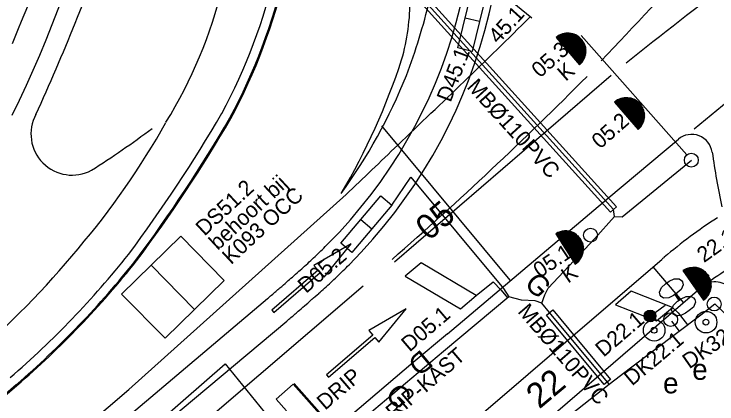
# Model space of a CAD drawing. Extents: x 81617 to 82144, y 454649 to 455150.
# Drawn here: x 81836.93 to 81870.9, y 454846.75 to 454865.61 of the extents above; entities that cross this region are included whole.
import ezdxf

# ---------------------------------------------------------------- set-up
doc = ezdxf.new("R2010")
doc.units = 0
for name, color, linetype in [('B-WE-OG-TOPOGRAFIE-G', 7, 'Continuous'), ('B-WE-VW-MARKERING-G', 7, 'Continuous'), ('N-OI-KL-VRI_KABEL_DETECTIE-G', 7, 'Continuous'), ('N-OI-KL-VRI_KABELGEUL-G', 7, 'Continuous'), ('N-OI-KL-VRI_LUS_DETECTIE-G', 7, 'Continuous'), ('N-OI-KL-VRI_LUS_DETECTIE-T18', 7, 'Continuous'), ('N-OI-KL-VRI_LUS_DETECTIE_SELECTIEF-G', 7, 'Continuous'), ('N-OI-KL-VRI_LUS_DETECTIE_SELECTIEF-T18', 7, 'Continuous'), ('N-OI-KL-VRI_MANTELBUIS-G', 7, 'Continuous'), ('N-OI-KL-VRI_MANTELBUIS-T18', 7, 'Continuous'), ('N-WE-VW-VRI_ARMATUUR-S', 7, 'Continuous'), ('N-WE-VW-VRI_ARMATUUR-T18', 7, 'Continuous'), ('N-WE-VW-VRI_KAST-T25', 7, 'Continuous'), ('N-WE-VW-VRI_LIGGER-G', 7, 'Continuous'), ('N-WE-VW-VRI_MAST-S', 7, 'Continuous'), ('N-WE-VW-VRI_RICHTINGNUMMER-T25', 7, 'Continuous')]:
    doc.layers.add(name, color=color, linetype=linetype)

msp = doc.modelspace()

# ---------------------------------------------------------------- linework, layer by layer
at = {"layer": 'B-WE-OG-TOPOGRAFIE-G'}
for p, q in [((81865.678, 454856.743), (81869.042, 454859.555)), ((81857.883, 454850.147), (81865.678, 454856.743)), ((81841.457, 454845.317), (81849.178, 454851.845)), ((81842.185, 454844.105), (81850.112, 454850.755)), ((81805.998, 454821.061), (81837.039, 454847.68))]:
    msp.add_line(p, q, dxfattribs=at)
for points in [[(81844.903, 454886.604), (81839.743, 454871.882), (81839.482, 454871.138), (81839.219, 454870.396), (81838.954, 454869.656), (81838.687, 454868.917), (81838.416, 454868.18), (81838.141, 454867.445), (81837.861, 454866.713), (81837.575, 454865.984), (81837.282, 454865.256), (81837.135, 454864.898), (81836.833, 454864.175)], [(81846.257, 454886.129), (81841.097, 454871.407), (81840.835, 454870.661), (81840.571, 454869.915), (81840.304, 454869.17), (81840.035, 454868.425), (81839.761, 454867.681), (81839.483, 454866.937), (81839.199, 454866.195), (81838.909, 454865.455), (81838.612, 454864.716), (81838.461, 454864.348), (81838.153, 454863.613), (81837.836, 454862.881), (81837.509, 454862.152), (81837.173, 454861.427), (81836.825, 454860.707)], [(81800.623, 454800), (81801.004, 454800.325), (81803.562, 454802.106), (81806.327, 454803.545), (81807.843, 454804.154), (81811.662, 454806.006), (81813.175, 454806.868), (81815.707, 454808.644), (81816.429, 454809.247), (81868.254, 454853.758)], [(81870.182, 454852.409), (81817.99, 454807.424), (81817.086, 454806.655), (81814.618, 454804.918), (81812.282, 454803.586), (81808.553, 454801.84), (81808.014, 454801.627)], [(81857.884, 454850.147), (81856.226, 454848.756), (81836.105, 454831.612)]]:
    msp.add_lwpolyline(points, dxfattribs=at)
for centre, radius, start, end in [((81834.856, 454871.629), 25.75, 315.1816, 14.1581), ((81834.856, 454871.629), 24.315, 315.1816, 14.1581), ((81744.949, 454903.377), 102.333, 335.38677, 340.77263), ((81821.582, 454874.325), 28.769, 331.9437, 346.7819), ((81821.582, 454874.325), 29.219, 331.9437, 346.7819), ((81824.821, 454872.343), 22.839, 328.39, 346.2989), ((81783.595, 454897.814), 73.395, 323.31793, 329.72379), ((81839.74, 454859.812), 1.994, 151.7295, 298.0081), ((81783.595, 454897.814), 73.845, 323.31793, 329.72379), ((81811.007, 454878.951), 38.102, 319.6035, 330.8163), ((81814.671, 454898.789), 48.33, 302.5532, 306.7699), ((81869.683, 454858.788), 1, 8.1206, 129.8961), ((81909.402, 454864.455), 39.12, 188.1206, 192.063), ((81883.766, 454835.824), 23.708, 122.7903, 130.5415), ((81834.293, 454872.188), 25.109, 314.3259, 315.1816), ((81807.049, 454881.413), 42.717, 310.5127, 320.5293), ((81831.414, 454875.136), 29.23, 313.5314, 314.3259), ((81807.67, 454881.636), 44.445, 310.8557, 321.5233), ((81807.67, 454881.636), 44.895, 310.8557, 321.5233), ((81825.018, 454881.985), 38.601, 312.248, 312.8592), ((81829.656, 454876.987), 31.783, 312.8592, 313.5314), ((81883.838, 454834.715), 24.607, 128.9896, 129.2958), ((81822.016, 454885.29), 43.065, 311.7591, 312.248), ((81834.293, 454872.188), 26.544, 314.3259, 315.1816), ((81813.097, 454895.28), 56.458, 311.3313, 311.7591), ((81831.414, 454875.136), 30.665, 313.5314, 314.3259), ((81878.198, 454841.916), 13.204, 120.9031, 127.375), ((81782.192, 454930.722), 103.482, 310.78124, 311.0257), ((81806.807, 454902.432), 65.982, 311.0257, 311.33128), ((81825.018, 454881.985), 40.036, 312.248, 312.8592), ((81829.656, 454876.987), 33.218, 312.8592, 313.5314), ((81870.835, 454851.651), 1, 35.4028, 130.7582), ((81768.584, 454946.497), 124.315, 310.65901, 310.78124), ((81822.016, 454885.29), 44.5, 311.7591, 312.248), ((81524.251, 455230.972), 499.315, 310.5979, 310.65901), ((81813.097, 454895.28), 57.893, 311.33128, 311.75909), ((81806.807, 454902.432), 67.417, 311.0257, 311.33128), ((81768.584, 454946.497), 125.75, 310.65901, 310.78124), ((81782.192, 454930.722), 104.917, 310.78124, 311.0257), ((81524.251, 455230.972), 500.75, 310.5979, 310.65901)]:
    msp.add_arc(centre, radius, start, end, dxfattribs=at)
at = {"layer": 'B-WE-VW-MARKERING-G'}
for p, q in [((81869.8, 454860.056), (81874.825, 454864.194)), ((81855.317, 454853.619), (81865.787, 454862.653)), ((81854.691, 454860.197), (81860.888, 454852.73)), ((81867.811, 454853.377), (81869.284, 454851.635)), ((81846.116, 454845.885), (81853.81, 454852.455)), ((81799.634, 454815.526), (81837.071, 454847.642))]:
    msp.add_line(p, q, dxfattribs=at)
msp.add_lwpolyline([(81801.861, 454812.865), (81812.709, 454822.091), (81823.285, 454831.011), (81833.469, 454839.753), (81842.474, 454847.451), (81852.979, 454856.88)], dxfattribs=at)
for points in [[(81853.227, 454854.493), (81851.427, 454853.442), (81851.623, 454853.214), (81849.385, 454851.292), (81849.482, 454851.178), (81851.721, 454853.1), (81851.916, 454852.873)], [(81855.876, 454851.355), (81854.076, 454850.304), (81854.272, 454850.077), (81852.034, 454848.155), (81852.131, 454848.041), (81854.37, 454849.963), (81854.565, 454849.735)]]:
    msp.add_lwpolyline(points, close=True, dxfattribs=at)
for centre, radius, start, end in [((81999.362, 454697.85), 212.13, 125.19968, 128.77534), ((81664.878, 455054.559), 277.009, 316.35043, 317.79319), ((81821.582, 454874.325), 29.269, 331.9437, 346.7819), ((81845.809, 454866.259), 10.261, 343.8323, 0.6213), ((81823.555, 454874.579), 34.479, 339.7444, 346.0669), ((81512.43, 455220.159), 497.913, 313.54801, 314.57127), ((81824.431, 454873.61), 32.859, 329.5018, 341.9003), ((81830.91, 454872.739), 26.954, 324.0988, 338), ((81737.068, 454988.961), 179.553, 311.14097, 315.26873), ((81783.595, 454897.814), 73.895, 323.31793, 329.72379), ((81783.595, 454897.814), 73.895, 323.31793, 329.72379), ((81697.039, 455021.878), 227.028, 313.38316, 314.25554), ((81807.67, 454881.636), 44.945, 310.8557, 321.5233)]:
    msp.add_arc(centre, radius, start, end, dxfattribs=at)
at = {"layer": 'N-OI-KL-VRI_KABEL_DETECTIE-G'}
msp.add_line((81868.754, 454851.421), (81869.03, 454851.16), dxfattribs=at)
for points in [[(81855.198, 454856.363), (81856.111, 454857.715), (81856.111, 454857.715), (81860.586, 454852.335)], [(81859.274, 454851.998), (81860.089, 454852.659), (81860.471, 454852.247)], [(81841.927, 454844.135), (81847.132, 454848.689), (81850.902, 454844.037)]]:
    msp.add_lwpolyline(points, dxfattribs=at)
at = {"layer": 'N-OI-KL-VRI_KABELGEUL-G'}
msp.add_line((81869.03, 454851.16), (81869.475, 454850.571), dxfattribs=at)
for points in [[(81862.44, 454851.616), (81862.582, 454852.027), (81862.754, 454852.346), (81865.008, 454854.754), (81865.955, 454855.815), (81865.903, 454856.153), (81846.599, 454877.513), (81846.252, 454877.634), (81845.96, 454877.281), (81846.114, 454876.473)], [(81870.802, 454851.587), (81872.685, 454849.803), (81872.834, 454849.851), (81878.298, 454853.089), (81882.037, 454855.056), (81886.495, 454859.072)], [(81865.955, 454855.815), (81866.324, 454855.794), (81869.674, 454858.544)], [(81860.586, 454852.335), (81860.85, 454851.931)], [(81860.471, 454852.247), (81860.783, 454851.875)], [(81865.692, 454847.708), (81862.812, 454851.166), (81862.44, 454851.616), (81862.125, 454851.74), (81861.458, 454851.771), (81860.85, 454851.931), (81857.688, 454849.285), (81854.312, 454846.452), (81850.918, 454843.526), (81850.644, 454843.845)], [(81870.121, 454851.062), (81870.802, 454851.587)], [(81831.652, 454818.786), (81838.237, 454824.448), (81844.551, 454829.887), (81846.588, 454831.607), (81850.757, 454835.251), (81862.252, 454844.975), (81865.692, 454847.708), (81866.725, 454848.497), (81870.121, 454851.062)], [(81868.713, 454850.754), (81869.077, 454850.271)]]:
    msp.add_lwpolyline(points, dxfattribs=at)
at = {"layer": 'N-OI-KL-VRI_LUS_DETECTIE-G'}
for p, q in [((81858.741, 454865.428), (81859.421, 454865.262)), ((81853.691, 454855.675), (81854.225, 454855.221)), ((81856.602, 454853.572), (81855.839, 454852.924)), ((81859.274, 454851.998), (81856.602, 454853.572)), ((81855.839, 454852.924), (81858.509, 454851.351)), ((81858.509, 454851.351), (81859.274, 454851.998)), ((81866.765, 454852.196), (81866.003, 454851.547)), ((81868.754, 454851.421), (81866.765, 454852.196)), ((81866.003, 454851.547), (81867.989, 454850.774)), ((81867.989, 454850.774), (81868.754, 454851.421))]:
    msp.add_line(p, q, dxfattribs=at)
for points in [[(81859.066, 454863.805), (81858.387, 454863.97), (81859.095, 454866.885), (81859.776, 454866.72)], [(81853.252, 454854.079), (81852.719, 454854.533), (81854.664, 454856.817), (81855.198, 454856.363)]]:
    msp.add_lwpolyline(points, close=True, dxfattribs=at)
at = {"layer": 'N-OI-KL-VRI_LUS_DETECTIE_SELECTIEF-G'}
for p, q in [((81844.984, 454854.865), (81842.128, 454852.065)), ((81847.084, 454852.724), (81844.984, 454854.865)), ((81843.556, 454853.465), (81845.656, 454851.323)), ((81844.229, 454849.923), (81847.084, 454852.724)), ((81842.128, 454852.065), (81844.229, 454849.923))]:
    msp.add_line(p, q, dxfattribs=at)
at = {"layer": 'N-OI-KL-VRI_MANTELBUIS-G'}
for points in [[(81866.052, 454856.287), (81865.755, 454856.019), (81846.451, 454877.379), (81846.747, 454877.647)], [(81865.763, 454847.936), (81865.455, 454847.68), (81862.658, 454851.038), (81862.966, 454851.294)]]:
    msp.add_lwpolyline(points, close=True, dxfattribs=at)
at = {"layer": 'N-WE-VW-VRI_ARMATUUR-S'}
for p, q in [((81860.603, 454866.537), (81861.949, 454865.424)), ((81863.177, 454864.521), (81864.31, 454863.197)), ((81863.202, 454864.537), (81864.331, 454863.218)), ((81863.227, 454864.554), (81864.352, 454863.24)), ((81863.254, 454864.571), (81864.37, 454863.262)), ((81863.28, 454864.585), (81864.39, 454863.287)), ((81863.306, 454864.6), (81864.408, 454863.312)), ((81863.337, 454864.614), (81864.425, 454863.336)), ((81863.364, 454864.625), (81864.443, 454863.364)), ((81863.394, 454864.639), (81864.459, 454863.391)), ((81863.423, 454864.648), (81864.473, 454863.418)), ((81863.454, 454864.658), (81864.487, 454863.446)), ((81863.486, 454864.665), (81864.501, 454863.478)), ((81863.519, 454864.674), (81864.513, 454863.51)), ((81863.553, 454864.68), (81864.526, 454863.541)), ((81863.588, 454864.686), (81864.536, 454863.575)), ((81863.625, 454864.689), (81864.545, 454863.611)), ((81863.663, 454864.691), (81864.553, 454863.648)), ((81863.701, 454864.692), (81864.56, 454863.686)), ((81863.741, 454864.691), (81864.565, 454863.726)), ((81863.784, 454864.687), (81864.571, 454863.769)), ((81863.828, 454864.682), (81864.57, 454863.813)), ((81863.876, 454864.675), (81864.57, 454863.863)), ((81863.924, 454864.662), (81864.566, 454863.91)), ((81863.98, 454864.646), (81864.559, 454863.968)), ((81864.036, 454864.623), (81864.546, 454864.029)), ((81864.102, 454864.593), (81864.525, 454864.1)), ((81864.183, 454864.544), (81864.491, 454864.186)), ((81863.13, 454864.483), (81864.265, 454863.154)), ((81863.154, 454864.501), (81864.286, 454863.175)), ((81864.317, 454864.432), (81864.403, 454864.335)), ((81866.135, 454861.469), (81867.245, 454860.189)), ((81866.165, 454861.484), (81867.261, 454860.213)), ((81866.192, 454861.495), (81867.279, 454860.241)), ((81866.222, 454861.509), (81867.295, 454860.268)), ((81866.251, 454861.518), (81867.309, 454860.295)), ((81866.282, 454861.528), (81867.323, 454860.323)), ((81866.314, 454861.536), (81867.336, 454860.355)), ((81866.347, 454861.545), (81867.348, 454860.387)), ((81866.381, 454861.552), (81867.361, 454860.418)), ((81866.416, 454861.557), (81867.371, 454860.452)), ((81866.453, 454861.56), (81867.38, 454860.488)), ((81866.49, 454861.563), (81867.388, 454860.525)), ((81866.529, 454861.564), (81867.394, 454860.563)), ((81866.569, 454861.563), (81867.399, 454860.603)), ((81866.612, 454861.56), (81867.404, 454860.646)), ((81866.656, 454861.555), (81867.403, 454860.69)), ((81866.704, 454861.548), (81867.403, 454860.74)), ((81866.752, 454861.535), (81867.398, 454860.788)), ((81866.808, 454861.52), (81867.391, 454860.845)), ((81866.864, 454861.497), (81867.378, 454860.906)), ((81866.93, 454861.467), (81867.356, 454860.977)), ((81865.959, 454861.352), (81867.102, 454860.029)), ((81865.983, 454861.37), (81867.124, 454860.051)), ((81866.006, 454861.389), (81867.147, 454860.072)), ((81866.031, 454861.406), (81867.168, 454860.094)), ((81866.056, 454861.423), (81867.189, 454860.116)), ((81866.083, 454861.441), (81867.206, 454860.138)), ((81866.108, 454861.454), (81867.227, 454860.164)), ((81867.012, 454861.419), (81867.322, 454861.063)), ((81867.147, 454861.308), (81867.233, 454861.212)), ((81863.162, 454855.015), (81864.097, 454853.544)), ((81863.189, 454855.027), (81864.12, 454853.562)), ((81863.216, 454855.041), (81864.144, 454853.581)), ((81863.246, 454855.054), (81864.165, 454853.6)), ((81863.273, 454855.064), (81864.189, 454853.622)), ((81863.301, 454855.075), (81864.21, 454853.644)), ((81863.333, 454855.084), (81864.23, 454853.666)), ((81863.362, 454855.092), (81864.252, 454853.691)), ((81863.393, 454855.101), (81864.272, 454853.715)), ((81863.423, 454855.106), (81864.289, 454853.74)), ((81863.456, 454855.111), (81864.307, 454853.766)), ((81863.488, 454855.114), (81864.325, 454853.795)), ((81863.522, 454855.118), (81864.342, 454853.826)), ((81863.557, 454855.12), (81864.359, 454853.854)), ((81863.592, 454855.12), (81864.374, 454853.886)), ((81863.629, 454855.118), (81864.388, 454853.92)), ((81863.667, 454855.115), (81864.401, 454853.956)), ((81863.705, 454855.11), (81864.413, 454853.993)), ((81863.745, 454855.104), (81864.424, 454854.032)), ((81863.787, 454855.093), (81864.436, 454854.073)), ((81863.829, 454855.083), (81864.441, 454854.117)), ((81863.876, 454855.068), (81864.448, 454854.166)), ((81863.922, 454855.049), (81864.45, 454854.214)), ((81863.974, 454855.025), (81864.452, 454854.272)), ((81863.11, 454854.984), (81864.046, 454853.508)), ((81863.136, 454854.999), (81864.07, 454853.526)), ((81864.027, 454854.995), (81864.448, 454854.334)), ((81864.087, 454854.955), (81864.437, 454854.408)), ((81864.161, 454854.895), (81864.415, 454854.498)), ((81864.278, 454854.766), (81864.349, 454854.658)), ((81869.475, 454853.309), (81870.428, 454851.929)), ((81869.503, 454853.319), (81870.449, 454851.952)), ((81869.536, 454853.329), (81870.468, 454851.98)), ((81869.565, 454853.335), (81870.483, 454852.005)), ((81869.596, 454853.342), (81870.501, 454852.031)), ((81869.63, 454853.345), (81870.519, 454852.062)), ((81869.663, 454853.351), (81870.532, 454852.092)), ((81869.697, 454853.354), (81870.549, 454852.12)), ((81869.735, 454853.355), (81870.562, 454852.154)), ((81869.771, 454853.357), (81870.575, 454852.189)), ((81869.809, 454853.354), (81870.588, 454852.223)), ((81869.847, 454853.352), (81870.597, 454852.262)), ((81869.887, 454853.347), (81870.608, 454852.303)), ((81869.929, 454853.336), (81870.617, 454852.342)), ((81869.972, 454853.329), (81870.621, 454852.389)), ((81870.019, 454853.314), (81870.625, 454852.437)), ((81869.257, 454853.2), (81870.251, 454851.763)), ((81869.281, 454853.217), (81870.274, 454851.78)), ((81869.307, 454853.233), (81870.298, 454851.801)), ((81869.334, 454853.246), (81870.322, 454851.82)), ((81869.359, 454853.262), (81870.345, 454851.839)), ((81869.389, 454853.275), (81870.366, 454851.861)), ((81869.417, 454853.288), (81870.389, 454851.881)), ((81869.445, 454853.301), (81870.408, 454851.906)), ((81870.064, 454853.298), (81870.627, 454852.483)), ((81870.118, 454853.276), (81870.625, 454852.543)), ((81870.173, 454853.249), (81870.618, 454852.605)), ((81870.236, 454853.211), (81870.605, 454852.676)), ((81870.311, 454853.155), (81870.58, 454852.765)), ((81870.433, 454853.028), (81870.508, 454852.923)), ((81868.418, 454852.565), (81868.588, 454852.68)), ((81868.588, 454852.68), (81868.829, 454852.795)), ((81868.829, 454852.795), (81869.073, 454852.806)), ((81869.073, 454852.806), (81869.19, 454852.726)), ((81869.19, 454852.726), (81869.239, 454852.65)), ((81869.239, 454852.65), (81869.276, 454852.516)), ((81868.125, 454852.151), (81868.221, 454852.377)), ((81868.221, 454852.377), (81868.418, 454852.565)), ((81869.178, 454852.289), (81868.98, 454852.115)), ((81869.276, 454852.516), (81869.178, 454852.289)), ((81868.161, 454852.015), (81868.125, 454852.151)), ((81868.212, 454851.941), (81868.161, 454852.015)), ((81868.799, 454851.993), (81868.573, 454851.873)), ((81868.98, 454852.115), (81868.799, 454851.993)), ((81868.875, 454852.042), (81869.07, 454851.757)), ((81868.929, 454852.075), (81869.126, 454851.792)), ((81869.418, 454851.943), (81869.665, 454851.953)), ((81869.665, 454851.953), (81869.779, 454851.876)), ((81868.326, 454851.86), (81868.212, 454851.941)), ((81868.573, 454851.873), (81868.326, 454851.86)), ((81868.808, 454851.526), (81869.003, 454851.712)), ((81869.003, 454851.712), (81869.172, 454851.828)), ((81869.172, 454851.828), (81869.418, 454851.943)), ((81869.864, 454851.665), (81869.765, 454851.435)), ((81869.779, 454851.876), (81869.828, 454851.801)), ((81869.828, 454851.801), (81869.864, 454851.665)), ((81867.911, 454851.173), (81868.408, 454851.527)), ((81868.715, 454851.302), (81868.808, 454851.526)), ((81868.751, 454851.166), (81868.715, 454851.302)), ((81869.765, 454851.435), (81869.567, 454851.262)), ((81868.803, 454851.089), (81868.751, 454851.166)), ((81868.915, 454851.008), (81868.803, 454851.089)), ((81869.158, 454851.02), (81868.915, 454851.008)), ((81869.387, 454851.137), (81869.158, 454851.02)), ((81869.567, 454851.262), (81869.387, 454851.137))]:
    msp.add_line(p, q, dxfattribs=at)
msp.add_lwpolyline([(81850.491, 454845.968), (81851, 454845.391), (81851.83, 454846.125), (81850.429, 454847.709), (81849.599, 454846.976), (81850.095, 454846.415)], dxfattribs=at)
for centre, radius in [((81867.67, 454851.003), 0.286), ((81867.67, 454851.003), 0.256), ((81867.67, 454851.003), 0.226), ((81867.67, 454851.003), 0.196), ((81867.67, 454851.003), 0.166), ((81867.67, 454851.003), 0.136), ((81867.67, 454851.003), 0.106), ((81867.67, 454851.003), 0.0765), ((81867.67, 454851.003), 0.0465), ((81867.67, 454851.003), 0.0165), ((81870.378, 454850.703), 0.522), ((81867.871, 454850.307), 0.522), ((81870.373, 454850.706), 0.141), ((81867.865, 454850.311), 0.141)]:
    msp.add_circle(centre, radius, dxfattribs=at)
for centre, start, end in [((81863.697, 454863.819), 310.4895, 130.4895), ((81866.53, 454860.691), 310.8473, 130.8473), ((81863.578, 454854.246), 302.3719, 122.3719), ((81869.753, 454852.482), 304.6317, 124.6317)]:
    msp.add_arc(centre, 0.873, start, end, dxfattribs=at)
at = {"layer": 'N-WE-VW-VRI_LIGGER-G'}
for p, q in [((81864.339, 454864.577), (81869.45, 454858.796)), ((81850.466, 454847.739), (81852.9, 454844.987))]:
    msp.add_line(p, q, dxfattribs=at)
at = {"layer": 'N-WE-VW-VRI_MAST-S'}
for centre in [(81869.665, 454858.539), (81864.796, 454854.91), (81870.767, 454851.581), (81868.667, 454850.828)]:
    msp.add_circle(centre, 0.335, dxfattribs=at)

# ---------------------------------------------------------------- texts
at = {"layer": 'B-WE-OG-TOPOGRAFIE-G'}
for s, rotation, p in [('G', 314.2792, (81861.551, 454852.519)), ('D', 219.9364, (81856.617, 454849.416)), ('G', 314.2792, (81854.824, 454847.144))]:
    msp.add_text(s, height=1, rotation=rotation, dxfattribs=at).set_placement(p)
for p in [(81869.712, 454847.912), (81868.301, 454847.258)]:
    msp.add_text('e', height=1, dxfattribs=at).set_placement(p)
at = {"layer": 'N-OI-KL-VRI_LUS_DETECTIE-T18'}
for s, rotation, p in [('D45.1', 69.1443, (81858.03, 454861.303)), ('D05.2', 40.5993, (81851.041, 454852.063)), ('D05.1', 40.5993, (81856.047, 454849.233)), ('D22.1', 40.5993, (81865.425, 454848.983))]:
    msp.add_text(s, height=0.75, rotation=rotation, dxfattribs=at).set_placement(p)
at = {"layer": 'N-OI-KL-VRI_LUS_DETECTIE_SELECTIEF-T18'}
for s, p in [('behoort bij', (81846.779, 454854.146)), ('DS51.2', (81846.135, 454854.84)), ('K093 OCC', (81847.417, 454853.459))]:
    msp.add_text(s, height=0.75, rotation=42.8601, dxfattribs=at).set_placement(p)
at = {"layer": 'N-OI-KL-VRI_MANTELBUIS-T18'}
for rotation, p in [(312.11, (81858.783, 454862.064)), (310.69, (81861.238, 454851.2))]:
    msp.add_text('MB%%C110PVC', height=0.75, rotation=rotation, dxfattribs=at).set_placement(p)
at = {"layer": 'N-WE-VW-VRI_ARMATUUR-S'}
for rotation, p in [(41.1601, (81863.595, 454862.325)), (34.3572, (81863.703, 454852.56))]:
    msp.add_text('K', height=0.75, rotation=rotation, dxfattribs=at).set_placement(p)
at = {"layer": 'N-WE-VW-VRI_ARMATUUR-T18'}
for s, rotation, p in [('45.1', 47.6296, (81860.337, 454864.127)), ('05.3', 41.4368, (81862.35, 454862.492)), ('05.2', 41.2872, (81865.254, 454859.052)), ('22.1', 35.3763, (81870.277, 454853.558)), ('05.1', 33.823, (81862.344, 454852.82)), ('DK32.1', 34.6846, (81869.567, 454848.415)), ('DK22.1', 40.0117, (81866.799, 454847.592)), ('DRIP', 40.7326, (81851.966, 454846.416))]:
    msp.add_text(s, height=0.75, rotation=rotation, dxfattribs=at).set_placement(p)
at = {"layer": 'N-WE-VW-VRI_KAST-T25'}
msp.add_text('DRIP-KAST', height=0.75, rotation=40.7326, dxfattribs=at).set_placement((81854.747, 454845.477))
at = {"layer": 'N-WE-VW-VRI_RICHTINGNUMMER-T25'}
for s, p in [('05', (81856.978, 454854.605)), ('22', (81862.319, 454846.475))]:
    msp.add_text(s, height=1.2, rotation=40, dxfattribs=at).set_placement(p)

doc.saveas('drawing.dxf')
